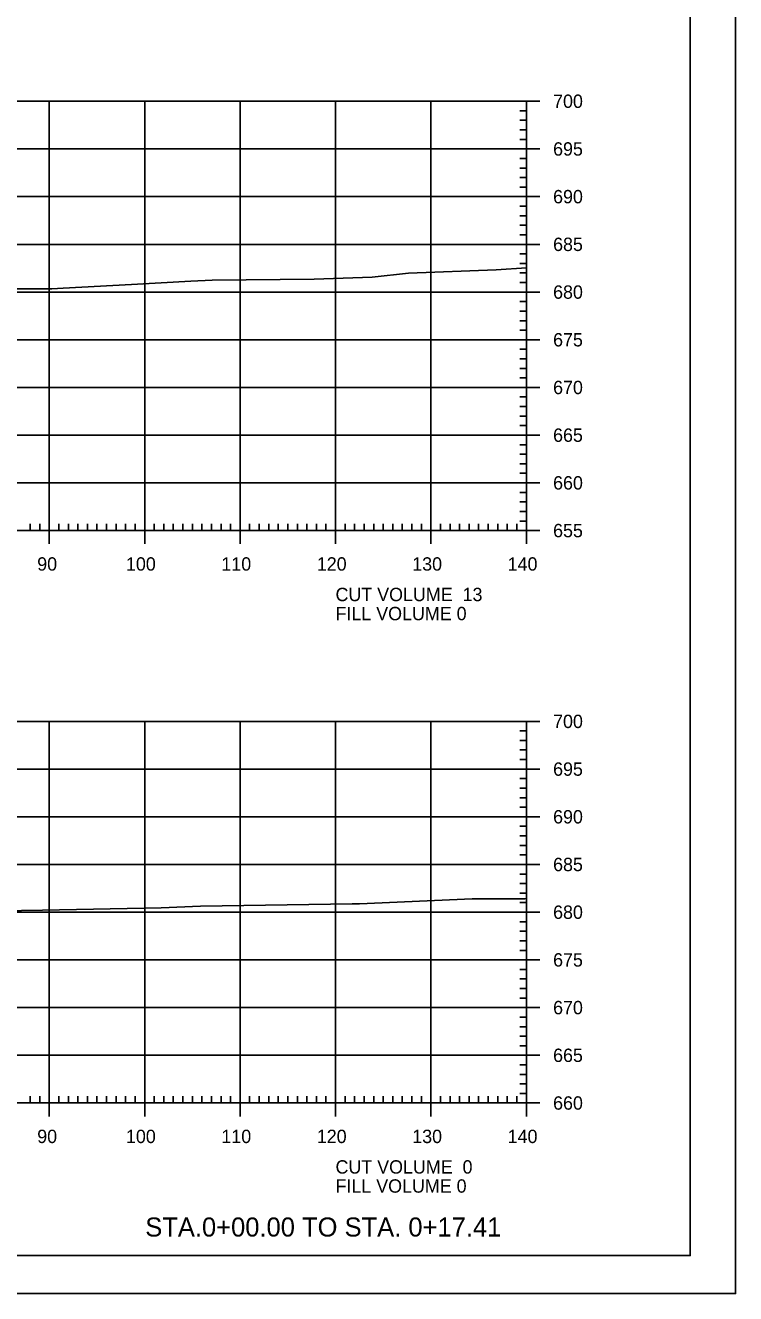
# Model space of a CAD drawing. Extents: x 1360146 to 1361431, y 631444 to 632352.
# Drawn here: x 1361329.1 to 1361403.5, y 631924.1 to 632057 of the extents above; entities that cross this region are included whole.
import ezdxf

# ---------------------------------------------------------------- set-up
doc = ezdxf.new("R2010")
doc.units = 0
for name, color, linetype in [('R_Axis', 7, 'Continuous'), ('R_Axis Annot', 7, 'Continuous'), ('R_Border', 7, 'Continuous'), ('R_Draft', 7, 'Continuous'), ('R_Exist Surface', 7, 'Continuous'), ('R_Grid', 7, 'Continuous'), ('R_No Plot', 7, 'Continuous')]:
    doc.layers.add(name, color=color, linetype=linetype)

msp = doc.modelspace()

# ---------------------------------------------------------------- linework, layer by layer
at = {"layer": 'R_Axis'}
for p, q in [((1361381.6, 632048.09), (1361380.9, 632048.09)), ((1361381.6, 632004.09), (1361381.6, 632049.09)), ((1361383, 632049.09), (1361381.6, 632049.09)), ((1361381.6, 632047.09), (1361380.9, 632047.09)), ((1361381.6, 632046.09), (1361380.9, 632046.09)), ((1361381.6, 632045.09), (1361380.9, 632045.09)), ((1361383, 632044.09), (1361381.6, 632044.09)), ((1361381.6, 632043.09), (1361380.9, 632043.09)), ((1361381.6, 632042.09), (1361380.9, 632042.09)), ((1361381.6, 632041.09), (1361380.9, 632041.09)), ((1361381.6, 632040.09), (1361380.9, 632040.09)), ((1361383, 632039.09), (1361381.6, 632039.09)), ((1361381.6, 632038.09), (1361380.9, 632038.09)), ((1361381.6, 632037.09), (1361380.9, 632037.09)), ((1361381.6, 632036.09), (1361380.9, 632036.09)), ((1361381.6, 632035.09), (1361380.9, 632035.09)), ((1361383, 632034.09), (1361381.6, 632034.09)), ((1361381.6, 632033.09), (1361380.9, 632033.09)), ((1361381.6, 632032.09), (1361380.9, 632032.09)), ((1361381.6, 632031.09), (1361380.9, 632031.09)), ((1361381.6, 632030.09), (1361380.9, 632030.09)), ((1361381.6, 632028.09), (1361380.9, 632028.09)), ((1361383, 632029.09), (1361381.6, 632029.09)), ((1361381.6, 632027.09), (1361380.9, 632027.09)), ((1361381.6, 632026.09), (1361380.9, 632026.09)), ((1361381.6, 632025.09), (1361380.9, 632025.09)), ((1361383, 632024.09), (1361381.6, 632024.09)), ((1361381.6, 632023.09), (1361380.9, 632023.09)), ((1361381.6, 632022.09), (1361380.9, 632022.09)), ((1361381.6, 632021.09), (1361380.9, 632021.09)), ((1361381.6, 632020.09), (1361380.9, 632020.09)), ((1361383, 632019.09), (1361381.6, 632019.09)), ((1361381.6, 632018.09), (1361380.9, 632018.09)), ((1361381.6, 632017.09), (1361380.9, 632017.09)), ((1361381.6, 632016.09), (1361380.9, 632016.09)), ((1361381.6, 632015.09), (1361380.9, 632015.09)), ((1361383, 632014.09), (1361381.6, 632014.09)), ((1361381.6, 632013.09), (1361380.9, 632013.09)), ((1361381.6, 632012.09), (1361380.9, 632012.09)), ((1361381.6, 632011.09), (1361380.9, 632011.09)), ((1361381.6, 632010.09), (1361380.9, 632010.09)), ((1361381.6, 632008.09), (1361380.9, 632008.09)), ((1361383, 632009.09), (1361381.6, 632009.09)), ((1361381.6, 632007.09), (1361380.9, 632007.09)), ((1361381.6, 632006.09), (1361380.9, 632006.09)), ((1361101.6, 632004.09), (1361381.6, 632004.09)), ((1361329.6, 632004.09), (1361329.6, 632004.79)), ((1361330.6, 632004.09), (1361330.6, 632004.79)), ((1361331.6, 632002.69), (1361331.6, 632004.09)), ((1361332.6, 632004.09), (1361332.6, 632004.79)), ((1361333.6, 632004.09), (1361333.6, 632004.79)), ((1361334.6, 632004.09), (1361334.6, 632004.79)), ((1361335.6, 632004.09), (1361335.6, 632004.79)), ((1361336.6, 632004.09), (1361336.6, 632004.79)), ((1361337.6, 632004.09), (1361337.6, 632004.79)), ((1361338.6, 632004.09), (1361338.6, 632004.79)), ((1361339.6, 632004.09), (1361339.6, 632004.79)), ((1361340.6, 632004.09), (1361340.6, 632004.79)), ((1361341.6, 632002.69), (1361341.6, 632004.09)), ((1361342.6, 632004.09), (1361342.6, 632004.79)), ((1361343.6, 632004.09), (1361343.6, 632004.79)), ((1361344.6, 632004.09), (1361344.6, 632004.79)), ((1361345.6, 632004.09), (1361345.6, 632004.79)), ((1361346.6, 632004.09), (1361346.6, 632004.79)), ((1361347.6, 632004.09), (1361347.6, 632004.79)), ((1361348.6, 632004.09), (1361348.6, 632004.79)), ((1361349.6, 632004.09), (1361349.6, 632004.79)), ((1361350.6, 632004.09), (1361350.6, 632004.79)), ((1361351.6, 632002.69), (1361351.6, 632004.09)), ((1361352.6, 632004.09), (1361352.6, 632004.79)), ((1361353.6, 632004.09), (1361353.6, 632004.79)), ((1361354.6, 632004.09), (1361354.6, 632004.79)), ((1361355.6, 632004.09), (1361355.6, 632004.79)), ((1361356.6, 632004.09), (1361356.6, 632004.79)), ((1361357.6, 632004.09), (1361357.6, 632004.79)), ((1361358.6, 632004.09), (1361358.6, 632004.79)), ((1361359.6, 632004.09), (1361359.6, 632004.79)), ((1361360.6, 632004.09), (1361360.6, 632004.79)), ((1361361.6, 632002.69), (1361361.6, 632004.09)), ((1361362.6, 632004.09), (1361362.6, 632004.79)), ((1361363.6, 632004.09), (1361363.6, 632004.79)), ((1361364.6, 632004.09), (1361364.6, 632004.79)), ((1361365.6, 632004.09), (1361365.6, 632004.79)), ((1361366.6, 632004.09), (1361366.6, 632004.79)), ((1361367.6, 632004.09), (1361367.6, 632004.79)), ((1361368.6, 632004.09), (1361368.6, 632004.79)), ((1361369.6, 632004.09), (1361369.6, 632004.79)), ((1361370.6, 632004.09), (1361370.6, 632004.79)), ((1361371.6, 632002.69), (1361371.6, 632004.09)), ((1361372.6, 632004.09), (1361372.6, 632004.79)), ((1361373.6, 632004.09), (1361373.6, 632004.79)), ((1361374.6, 632004.09), (1361374.6, 632004.79)), ((1361375.6, 632004.09), (1361375.6, 632004.79)), ((1361376.6, 632004.09), (1361376.6, 632004.79)), ((1361377.6, 632004.09), (1361377.6, 632004.79)), ((1361378.6, 632004.09), (1361378.6, 632004.79)), ((1361379.6, 632004.09), (1361379.6, 632004.79)), ((1361380.6, 632004.09), (1361380.6, 632004.79)), ((1361381.6, 632005.09), (1361380.9, 632005.09)), ((1361381.6, 632002.69), (1361381.6, 632004.09)), ((1361383, 632004.09), (1361381.6, 632004.09)), ((1361381.6, 631944.09), (1361381.6, 631984.09)), ((1361383, 631984.09), (1361381.6, 631984.09)), ((1361381.6, 631983.09), (1361380.9, 631983.09)), ((1361381.6, 631982.09), (1361380.9, 631982.09)), ((1361381.6, 631981.09), (1361380.9, 631981.09)), ((1361381.6, 631980.09), (1361380.9, 631980.09)), ((1361383, 631979.09), (1361381.6, 631979.09)), ((1361381.6, 631978.09), (1361380.9, 631978.09)), ((1361381.6, 631977.09), (1361380.9, 631977.09)), ((1361381.6, 631976.09), (1361380.9, 631976.09)), ((1361381.6, 631975.09), (1361380.9, 631975.09)), ((1361383, 631974.09), (1361381.6, 631974.09)), ((1361381.6, 631973.09), (1361380.9, 631973.09)), ((1361381.6, 631972.09), (1361380.9, 631972.09)), ((1361381.6, 631971.09), (1361380.9, 631971.09)), ((1361381.6, 631970.09), (1361380.9, 631970.09)), ((1361381.6, 631968.09), (1361380.9, 631968.09)), ((1361383, 631969.09), (1361381.6, 631969.09)), ((1361381.6, 631967.09), (1361380.9, 631967.09)), ((1361381.6, 631966.09), (1361380.9, 631966.09)), ((1361381.6, 631965.09), (1361380.9, 631965.09)), ((1361383, 631964.09), (1361381.6, 631964.09)), ((1361381.6, 631963.09), (1361380.9, 631963.09)), ((1361381.6, 631962.09), (1361380.9, 631962.09)), ((1361381.6, 631961.09), (1361380.9, 631961.09)), ((1361381.6, 631960.09), (1361380.9, 631960.09)), ((1361383, 631959.09), (1361381.6, 631959.09)), ((1361381.6, 631958.09), (1361380.9, 631958.09)), ((1361381.6, 631957.09), (1361380.9, 631957.09)), ((1361381.6, 631956.09), (1361380.9, 631956.09)), ((1361381.6, 631955.09), (1361380.9, 631955.09)), ((1361383, 631954.09), (1361381.6, 631954.09)), ((1361381.6, 631953.09), (1361380.9, 631953.09)), ((1361381.6, 631952.09), (1361380.9, 631952.09)), ((1361381.6, 631951.09), (1361380.9, 631951.09)), ((1361381.6, 631950.09), (1361380.9, 631950.09)), ((1361383, 631949.09), (1361381.6, 631949.09)), ((1361381.6, 631948.09), (1361380.9, 631948.09)), ((1361381.6, 631947.09), (1361380.9, 631947.09)), ((1361381.6, 631946.09), (1361380.9, 631946.09)), ((1361329.6, 631944.09), (1361329.6, 631944.79)), ((1361330.6, 631944.09), (1361330.6, 631944.79)), ((1361332.6, 631944.09), (1361332.6, 631944.79)), ((1361333.6, 631944.09), (1361333.6, 631944.79)), ((1361334.6, 631944.09), (1361334.6, 631944.79)), ((1361335.6, 631944.09), (1361335.6, 631944.79)), ((1361336.6, 631944.09), (1361336.6, 631944.79)), ((1361337.6, 631944.09), (1361337.6, 631944.79)), ((1361338.6, 631944.09), (1361338.6, 631944.79)), ((1361339.6, 631944.09), (1361339.6, 631944.79)), ((1361340.6, 631944.09), (1361340.6, 631944.79)), ((1361342.6, 631944.09), (1361342.6, 631944.79)), ((1361343.6, 631944.09), (1361343.6, 631944.79)), ((1361344.6, 631944.09), (1361344.6, 631944.79)), ((1361345.6, 631944.09), (1361345.6, 631944.79)), ((1361346.6, 631944.09), (1361346.6, 631944.79)), ((1361347.6, 631944.09), (1361347.6, 631944.79)), ((1361348.6, 631944.09), (1361348.6, 631944.79)), ((1361349.6, 631944.09), (1361349.6, 631944.79)), ((1361350.6, 631944.09), (1361350.6, 631944.79)), ((1361352.6, 631944.09), (1361352.6, 631944.79)), ((1361353.6, 631944.09), (1361353.6, 631944.79)), ((1361354.6, 631944.09), (1361354.6, 631944.79)), ((1361355.6, 631944.09), (1361355.6, 631944.79)), ((1361356.6, 631944.09), (1361356.6, 631944.79)), ((1361357.6, 631944.09), (1361357.6, 631944.79)), ((1361358.6, 631944.09), (1361358.6, 631944.79)), ((1361359.6, 631944.09), (1361359.6, 631944.79)), ((1361360.6, 631944.09), (1361360.6, 631944.79)), ((1361362.6, 631944.09), (1361362.6, 631944.79)), ((1361363.6, 631944.09), (1361363.6, 631944.79)), ((1361364.6, 631944.09), (1361364.6, 631944.79)), ((1361365.6, 631944.09), (1361365.6, 631944.79)), ((1361366.6, 631944.09), (1361366.6, 631944.79)), ((1361367.6, 631944.09), (1361367.6, 631944.79)), ((1361368.6, 631944.09), (1361368.6, 631944.79)), ((1361369.6, 631944.09), (1361369.6, 631944.79)), ((1361370.6, 631944.09), (1361370.6, 631944.79)), ((1361372.6, 631944.09), (1361372.6, 631944.79)), ((1361373.6, 631944.09), (1361373.6, 631944.79)), ((1361374.6, 631944.09), (1361374.6, 631944.79)), ((1361375.6, 631944.09), (1361375.6, 631944.79)), ((1361376.6, 631944.09), (1361376.6, 631944.79)), ((1361377.6, 631944.09), (1361377.6, 631944.79)), ((1361378.6, 631944.09), (1361378.6, 631944.79)), ((1361379.6, 631944.09), (1361379.6, 631944.79)), ((1361380.6, 631944.09), (1361380.6, 631944.79)), ((1361381.6, 631945.09), (1361380.9, 631945.09)), ((1361101.6, 631944.09), (1361381.6, 631944.09)), ((1361331.6, 631942.69), (1361331.6, 631944.09)), ((1361341.6, 631942.69), (1361341.6, 631944.09)), ((1361351.6, 631942.69), (1361351.6, 631944.09)), ((1361361.6, 631942.69), (1361361.6, 631944.09)), ((1361371.6, 631942.69), (1361371.6, 631944.09)), ((1361381.6, 631942.69), (1361381.6, 631944.09)), ((1361383, 631944.09), (1361381.6, 631944.09))]:
    msp.add_line(p, q, dxfattribs=at)
at = {"layer": 'R_Border'}
for q in [(1361398.78, 632133.55), (1361082.6, 631928.09)]:
    msp.add_line((1361398.78, 631928.09), q, dxfattribs=at)
at = {"layer": 'R_Exist Surface'}
for points in [[(1361253.58, 632027.5), (1361260.88, 632028.05), (1361267.2, 632028.29), (1361282.88, 632029.21), (1361289.33, 632029.32), (1361305.17, 632029.39), (1361308.93, 632029.42), (1361312.36, 632029.44), (1361331.87, 632029.41), (1361333.05, 632029.48), (1361340.21, 632029.87), (1361346.43, 632030.23), (1361348.66, 632030.32), (1361359.35, 632030.44), (1361365.45, 632030.66), (1361369.26, 632031.08), (1361378.42, 632031.41), (1361381.6, 632031.63)], [(1361251.95, 631962.62), (1361257.64, 631963.05), (1361268.52, 631963.47), (1361275.2, 631963.86), (1361286.53, 631964.05), (1361294.89, 631964.08), (1361303.7, 631964.15), (1361311.75, 631964.22), (1361324.29, 631964.19), (1361330.9, 631964.29), (1361343.34, 631964.54), (1361347.44, 631964.73), (1361363.33, 631964.95), (1361363.54, 631964.96), (1361364.12, 631964.97), (1361375.92, 631965.49), (1361381.44, 631965.5), (1361381.6, 631965.51)]]:
    msp.add_lwpolyline(points, dxfattribs=at)
at = {"layer": 'R_Grid'}
for p, q in [((1361101.6, 632049.09), (1361381.6, 632049.09)), ((1361331.6, 632004.09), (1361331.6, 632049.09)), ((1361341.6, 632004.09), (1361341.6, 632049.09)), ((1361351.6, 632004.09), (1361351.6, 632049.09)), ((1361361.6, 632004.09), (1361361.6, 632049.09)), ((1361371.6, 632004.09), (1361371.6, 632049.09)), ((1361381.6, 632004.09), (1361381.6, 632049.09)), ((1361101.6, 632044.09), (1361381.6, 632044.09)), ((1361101.6, 632039.09), (1361381.6, 632039.09)), ((1361101.6, 632034.09), (1361381.6, 632034.09)), ((1361101.6, 632029.09), (1361381.6, 632029.09)), ((1361101.6, 632024.09), (1361381.6, 632024.09)), ((1361101.6, 632019.09), (1361381.6, 632019.09)), ((1361101.6, 632014.09), (1361381.6, 632014.09)), ((1361101.6, 632009.09), (1361381.6, 632009.09)), ((1361101.6, 632004.09), (1361381.6, 632004.09)), ((1361101.6, 631984.09), (1361381.6, 631984.09)), ((1361331.6, 631944.09), (1361331.6, 631984.09)), ((1361341.6, 631944.09), (1361341.6, 631984.09)), ((1361351.6, 631944.09), (1361351.6, 631984.09)), ((1361361.6, 631944.09), (1361361.6, 631984.09)), ((1361371.6, 631944.09), (1361371.6, 631984.09)), ((1361381.6, 631944.09), (1361381.6, 631984.09)), ((1361101.6, 631979.09), (1361381.6, 631979.09)), ((1361101.6, 631974.09), (1361381.6, 631974.09)), ((1361101.6, 631969.09), (1361381.6, 631969.09)), ((1361101.6, 631964.09), (1361381.6, 631964.09)), ((1361101.6, 631959.09), (1361381.6, 631959.09)), ((1361101.6, 631954.09), (1361381.6, 631954.09)), ((1361101.6, 631949.09), (1361381.6, 631949.09)), ((1361101.6, 631944.09), (1361381.6, 631944.09))]:
    msp.add_line(p, q, dxfattribs=at)
at = {"layer": 'R_No Plot'}
msp.add_line((1361070.2, 631924.11), (1361403.53, 631924.11), dxfattribs=at)
for points in [[(1361070.19, 632137.45), (1361403.53, 632137.45), (1361403.53, 631924.11), (1361070.19, 631924.11)], [(1361316.52, 632133.55), (1361316.52, 632123.67), (1361352.25, 632123.67), (1361352.25, 632120.75), (1361375.45, 632120.75), (1361375.45, 632096.42), (1361398.78, 632096.42), (1361398.78, 631928.09), (1361082.6, 631928.09), (1361082.6, 632133.55)]]:
    msp.add_lwpolyline(points, close=True, dxfattribs=at)

# ---------------------------------------------------------------- texts
at = {"layer": 'R_Axis Annot'}
for s, p in [('700', (1361384.4, 632048.39)), ('695', (1361384.4, 632043.39)), ('690', (1361384.4, 632038.39)), ('685', (1361384.4, 632033.39)), ('680', (1361384.4, 632028.39)), ('675', (1361384.4, 632023.39)), ('670', (1361384.4, 632018.39)), ('665', (1361384.4, 632013.39)), ('660', (1361384.4, 632008.39)), ('655', (1361384.4, 632003.39)), ('90', (1361330.34, 631999.89)), ('100', (1361339.64, 631999.89)), ('110', (1361349.64, 631999.89)), ('120', (1361359.64, 631999.89)), ('130', (1361369.64, 631999.89)), ('140', (1361379.64, 631999.89)), ('CUT VOLUME  13', (1361361.6, 631996.69)), ('FILL VOLUME 0', (1361361.6, 631994.69)), ('700', (1361384.4, 631983.39)), ('695', (1361384.4, 631978.39)), ('690', (1361384.4, 631973.39)), ('685', (1361384.4, 631968.39)), ('680', (1361384.4, 631963.39)), ('675', (1361384.4, 631958.39)), ('670', (1361384.4, 631953.39)), ('665', (1361384.4, 631948.39)), ('660', (1361384.4, 631943.39)), ('90', (1361330.34, 631939.89)), ('100', (1361339.64, 631939.89)), ('110', (1361349.64, 631939.89)), ('120', (1361359.64, 631939.89)), ('130', (1361369.64, 631939.89)), ('140', (1361379.64, 631939.89)), ('CUT VOLUME  0', (1361361.6, 631936.69)), ('FILL VOLUME 0', (1361361.6, 631934.69))]:
    msp.add_text(s, height=1.4, dxfattribs=at).set_placement(p)
at = {"layer": 'R_Draft'}
msp.add_text('STA.0+00.00 TO STA. 0+17.41', height=2, dxfattribs=at).set_placement((1361341.66, 631930.09))

doc.saveas('drawing.dxf')
